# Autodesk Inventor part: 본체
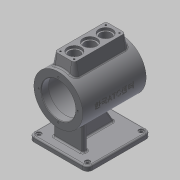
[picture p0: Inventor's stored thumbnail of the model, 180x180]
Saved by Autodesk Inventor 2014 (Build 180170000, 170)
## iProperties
Created: 2015-11
Part Number: 본체
Material: 일반
Document SubType Name: Modeling
Designer: mduedu
Density: 1 g/cm^3
Appearance: 기본값
Mass: 574.559 g
Surface Area: 1415.53 cm^2
Volume: 574.559 cm^3
Author: mduedu
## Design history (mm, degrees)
sketch "스케치2"
  geometry: C1 r 50 at (0, 0); 1 further point
  constraints: 1 centre point, 1 coincident
  dimensions: "d147" = 100 diameter of C1
extrude "돌출1" new body sketch "스케치2" stored distance "d12" = 130; taper "d13" = 0 deg
feature "쉘1" dims "d31" = 15, "d32" = 6, "d33" = 15
sketch "스케치5"
  geometry: C1 r 35 at (0, 0); 1 further point
  constraints: 1 centre point, 1 coincident
  dimensions: "d34" = 70 diameter of C1
extrude "돌출3" cut sketch "스케치5" stored distance "d36" = 3; taper "d37" = 0 deg
node "작업 평면1"
sketch "스케치6"
  geometry: L1 (-65, -60)-(65, -60); L2 (65, -60)-(65, 60); L3 (65, 60)-(-65, 60); L4 (-65, 60)-(-65, -60); L5 (-65, -60)-(65, 60); L6 (65, -60)-(-65, 60); 1 further point
  constraints: 12 end point, 2 midpoint, 2 parallel, 1 horizontal, 1 perpendicular
  dimensions: "d41" = 120 distance of L3.end L1.start; "d43" = 130 distance of L2.end L3.end
extrude "돌출4" join sketch "스케치6" distance "d44" = 10; taper "d45" = 0 deg
sketch "스케치19"
  geometry: L1 (-45, 30)-(-35, 30); L2 (-35, 30)-(-35, -30); L3 (-35, -30)-(-45, -30); L4 (-45, -30)-(-45, 30); L5 (-65, 60)-(-65, -60) reference; 2 further points
  constraints: 8 end point, 2 parallel, 1 horizontal, 1 horizontal alignment, 1 midpoint, 1 perpendicular
  dimensions: "d150" = 20 distance between parallel lines of L4 L5; "d151" = 10 distance of L1.start L1.end; "d152" = 60 distance of L3.end L1.start
extrude "돌출9" join sketch "스케치19" stored distance "d153" = 10; taper "d154" = 0 deg
sketch "스케치20"
  geometry: L1 (65, 35)-(50, 35) reference; L2 (50, 35)-(50, 44) reference; L3 (50, 44)-(-50, 44) reference; L4 (-50, 44)-(-50, 35) reference; L5 (-50, 35)-(-65, 35) reference; L6 (-65, 35)-(-65, 50) reference; L7 (-65, 50)-(65, 50) reference; L8 (65, 50)-(65, 35) reference; L9 (50, -35)-(65, -35) reference; L10 (65, -35)-(65, -50) reference; L11 (65, -50)-(45, -50) reference; L12 (45, -50)-(45, -90) reference; L13 (45, -90)-(65, -90) reference; L14 (65, -90)-(65, -100) reference; L15 (65, -100)-(-65, -100) reference; L16 (-65, -100)-(-65, -90) reference; L17 (-65, -90)-(35, -90) reference; L18 (35, -90)-(35, -50) reference; L19 (35, -50)-(-65, -50) reference; L20 (-65, -50)-(-65, -35) reference; L21 (-65, -35)-(-50, -35) reference; L22 (-50, -35)-(-50, -44) reference; L23 (-50, -44)-(50, -44) reference; L24 (50, -44)-(50, -35) reference; L25 (-45, -90)-(-21.906, -50); 1 further point
  constraints: 2 end point, 2 point on line
  dimensions: "d155" = 20 distance from line of L25.start L16; "d156" = 120 deg angle of L25 L17
feature "리브2" sketch "스케치20" dims "d157" = 1, "d158" = 10, "d159" = 0, "d160" = 0, "d161" = 1, "d162" = 1
fillet "모깎기21" dims "d163" = 3
fillet "모깎기22" dims "d164" = 3
fillet "모깎기23" dims "d165" = 3
sketch "스케치21" dims "d166" = 80
  geometry: 3 further points
  constraints: 2 horizontal alignment, 1 coincident, 2 other
hole "구멍6" sketch "스케치21" at (40, 0) diameter "d168" = 3.242; stored, may be unused: countersink angle "d172" = 90 deg, drill point angle "d174" = 118 deg; dims "d169" = 9, "d170" = 4, "d171" = 2, "d173" = 11
node "작업 평면2"
sketch "스케치13"
  geometry: L1 (-52.5, -20)-(52.5, -20); L2 (52.5, -20)-(52.5, 20); L3 (52.5, 20)-(-52.5, 20); L4 (-52.5, 20)-(-52.5, -20); L5 (-52.5, -20)-(52.5, 20); L6 (52.5, -20)-(-52.5, 20); 1 further point
  constraints: 12 end point, 2 midpoint, 2 parallel, 1 horizontal, 1 perpendicular
  dimensions: "d93" = 105 distance of L2.end L3.end; "d95" = 40 distance of L1.end L2.end
extrude "돌출8" join sketch "스케치13" stored distance "d96" = 80; taper "d97" = 0 deg
fillet "모깎기15" dims "d98" = 5
feature "면 기울기1" dims angle "d178" = 10 deg
fillet "모깎기24" dims "d179" = 3
sketch "스케치14"
  geometry: L1 (-52.5, 15)-(-52.5, -15) reference; L2 (52.5, -15)-(52.5, 15) reference; L3 (-52.5, 0)-(52.5, 0); 4 further points
  constraints: 2 end point, 2 midpoint, 2 point on line, 1 coincident
  dimensions: "d100" = 32 distance of point (-32, 0) point (0, 0); "d102" = 32 distance of point (32, 0) point (0, 0) (derived)
hole "구멍3" sketch "스케치14" at (-32, 0), (0, 0), (32, 0) diameter "d103" = 22; stored, may be unused: countersink angle "d107" = 90 deg, drill point angle "d109" = 118 deg; dims "d104" = 8, "d105" = 28, "d106" = 5, "d108" = 10
sketch "스케치15"
  geometry: L1 (46.5, -14)-(-46.5, -14); L2 (-46.5, -14)-(-46.5, 14); L3 (-46.5, 14)-(46.5, 14); L4 (46.5, 14)-(46.5, -14); L5 (46.5, -14)-(-46.5, 14); L6 (-46.5, -14)-(46.5, 14); L7 (47.5, 20)-(-47.5, 20) reference; L8 (-52.5, 15)-(-52.5, -15) reference; 5 further points
  constraints: 12 end point, 4 coincident, 2 midpoint, 2 parallel, 1 horizontal, 1 perpendicular
  dimensions: "d110" = 6 distance between parallel lines of L3 L7; "d111" = 6 distance between parallel lines of L2 L8
hole "구멍4" sketch "스케치15" at (-46.5, 14), (46.5, 14), (46.5, -14), (-46.5, -14) diameter "d112" = 3.242; stored, may be unused: countersink angle "d116" = 90 deg, drill point angle "d118" = 118 deg; dims "d113" = 10, "d114" = 28, "d115" = 5, "d117" = 13
node "작업 평면3"
sketch "스케치22"
  geometry: 2 further points
  constraints: 1 coincident, 1 other
feature "엠보싱3" sketch "스케치22" dims "d32" = 6, "d181" = 0.5, "d182" = 0
chamfer "모따기2" distance "d183" = 1; stored, may be unused: second distance "d184" = 2, angle "d185" = 45 deg
fillet "모깎기25" dims "d186" = 10
sketch "스케치23"
  geometry: L1 (55, 60)-(-55, 60) reference; L2 (65, -50)-(65, 50) reference; L3 (-55, -60)-(55, -60) reference; L4 (-65, 50)-(-65, -50) reference; A1 r 10 centre (-55, 50) between (-55, 60) and (-65, 50) reference; A2 r 10 centre (55, 50) between (65, 50) and (55, 60) reference; A3 r 10 centre (55, -50) between (55, -60) and (65, -50) reference; A4 r 10 centre (-55, -50) between (-65, -50) and (-55, -60) reference; 1 further point
hole "구멍7" sketch "스케치23" at (-55, 50), (-55, -50), (55, -50), (55, 50) diameter "d187" = 6; stored, may be unused: countersink angle "d191" = 90 deg, drill point angle "d193" = 118 deg; dims "d188" = 9, "d189" = 10, "d190" = 2, "d192" = 11
fillet "모깎기26" dims "d194" = 3
node "솔리드1"
pattern_circular "원형 패턴2" dims angle "d176" = 360 deg
mirror "대칭5"
node "투영된 루프2"
node "절단 모서리 투영1"
